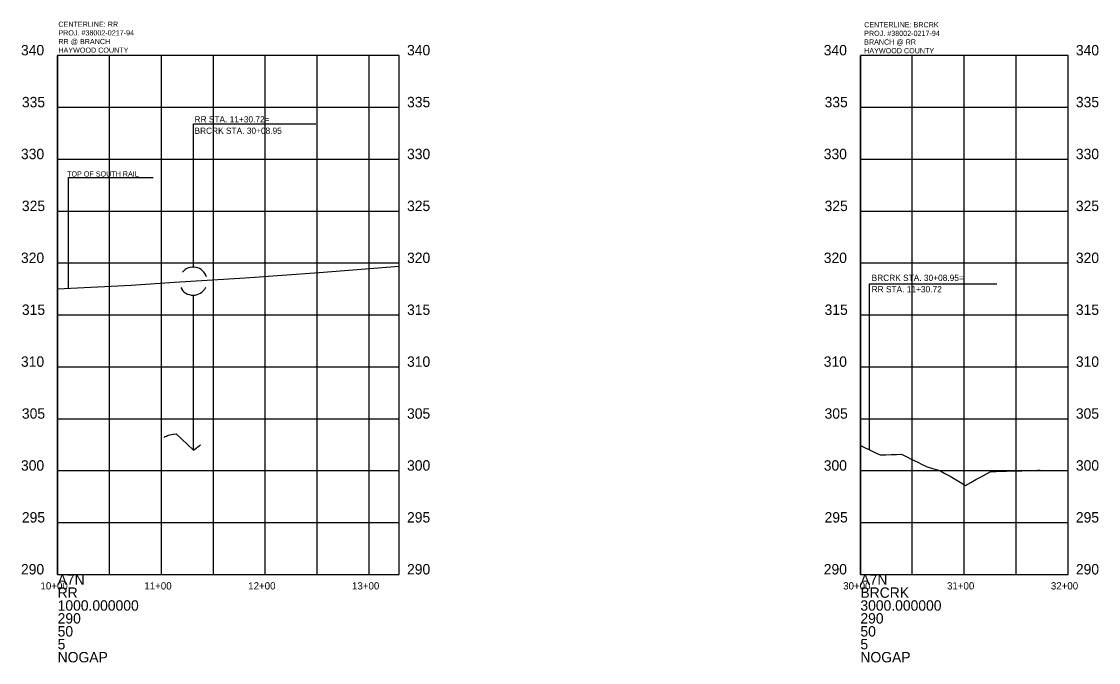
# Model space of a CAD drawing. Extents: x -200 to 952328, y -218 to 426868.
# Drawn here: x 949299 to 950336, y 425994 to 426611 of the extents above; entities that cross this region are included whole.
import ezdxf

# ---------------------------------------------------------------- set-up
doc = ezdxf.new("R2010")
doc.units = 0
for name, color, linetype in [('DESIGN - SHEET - Corner Text', 7, 'Continuous'), ('DESIGN - SHEET - Light Grid', 7, 'Continuous'), ('SURVEY - PROFILE - Drainage - Bridge Hydraulic Data with Text', 7, 'Continuous'), ('SURVEY - PROFILE - Existing Roads with Text', 7, 'Continuous'), ('SURVEY - PROFILE - Project Information and Notes', 7, 'Continuous')]:
    doc.layers.add(name, color=color, linetype=linetype)

msp = doc.modelspace()

# ---------------------------------------------------------------- linework, layer by layer
at = {"layer": 'DESIGN - SHEET - Light Grid'}
for p, q in [((949662.7, 426578.8), (949333.7, 426578.8)), ((949333.7, 426578.8), (949333.7, 426078.8)), ((949333.7, 426078.8), (949333.7, 426578.8)), ((949383.7, 426078.8), (949383.7, 426578.8)), ((949433.7, 426078.8), (949433.7, 426578.8)), ((949483.7, 426078.8), (949483.7, 426578.8)), ((949533.7, 426078.8), (949533.7, 426578.8)), ((949583.7, 426078.8), (949583.7, 426578.8)), ((949633.7, 426078.8), (949633.7, 426578.8)), ((949662.7, 426078.8), (949662.7, 426578.8)), ((950306.8, 426578.8), (950106.8, 426578.8)), ((950106.8, 426578.8), (950106.8, 426078.8)), ((950106.8, 426078.8), (950106.8, 426578.8)), ((950156.8, 426078.8), (950156.8, 426578.8)), ((950206.8, 426078.8), (950206.8, 426578.8)), ((950256.8, 426078.8), (950256.8, 426578.8)), ((950306.8, 426078.8), (950306.8, 426578.8)), ((949333.7, 426528.8), (949662.7, 426528.8)), ((950106.8, 426528.8), (950306.8, 426528.8)), ((949333.7, 426478.8), (949662.7, 426478.8)), ((950106.8, 426478.8), (950306.8, 426478.8)), ((949333.7, 426428.8), (949662.7, 426428.8)), ((950106.8, 426428.8), (950306.8, 426428.8)), ((949333.7, 426378.8), (949662.7, 426378.8)), ((950106.8, 426378.8), (950306.8, 426378.8)), ((949333.7, 426328.8), (949662.7, 426328.8)), ((950106.8, 426328.8), (950306.8, 426328.8)), ((949333.7, 426278.8), (949662.7, 426278.8)), ((950106.8, 426278.8), (950306.8, 426278.8)), ((949333.7, 426228.8), (949662.7, 426228.8)), ((950106.8, 426228.8), (950306.8, 426228.8)), ((949333.7, 426178.8), (949662.7, 426178.8)), ((950106.8, 426178.8), (950306.8, 426178.8)), ((949333.7, 426128.8), (949662.7, 426128.8)), ((950106.8, 426128.8), (950306.8, 426128.8)), ((949333.7, 426078.8), (949662.7, 426078.8)), ((949333.7, 426078.8), (949662.7, 426078.8)), ((949333.7, 426078.8), (949333.7, 426078.8)), ((950106.8, 426078.8), (950306.8, 426078.8)), ((950106.8, 426078.8), (950279.8, 426078.8)), ((950106.8, 426078.8), (950106.8, 426078.8))]:
    msp.add_line(p, q, dxfattribs=at)
at = {"layer": 'SURVEY - PROFILE - Drainage - Bridge Hydraulic Data with Text'}
for points in [[(949435.9, 426211.3), (949436.5, 426211.1), (949437.4, 426211.6), (949438.4, 426212.1), (949439.4, 426212.6), (949440.4, 426213.1), (949444.7, 426213.8), (949445.1, 426214), (949447.7, 426214.2), (949464.1, 426198.9), (949464.4, 426198.6), (949471.4, 426203.6)], [(950106.8, 426202.9), (950110.7, 426201.1), (950115.7, 426198.7), (950120.7, 426196.3), (950125.7, 426193.9), (950126.4, 426193.9), (950131.4, 426194), (950136.4, 426194.2), (950141.4, 426194.4), (950146.4, 426194.5), (950151.4, 426192.1), (950156.4, 426189.6), (950161.4, 426187.2), (950166.4, 426184.8), (950171.2, 426182.4), (950176.2, 426180.9), (950181.2, 426179.4), (950183.2, 426178.8), (950188.1, 426176.1), (950193.1, 426173.3), (950198, 426170.5), (950203, 426167.6), (950208.1, 426164.6), (950213.1, 426167.4), (950218.1, 426170.1), (950223.1, 426172.8), (950228.1, 426175.6), (950232.4, 426177.9), (950237.4, 426178.1), (950242.4, 426178.2), (950247.4, 426178.3), (950252.4, 426178.5), (950257.4, 426178.6), (950262.4, 426178.7), (950267.4, 426178.9), (950272.4, 426179), (950277.4, 426179.1), (950279.8, 426179.2)]]:
    msp.add_lwpolyline(points, dxfattribs=at)
at = {"layer": 'SURVEY - PROFILE - Existing Roads with Text'}
for p, q in [((949464.4, 426374.7), (949464.4, 426512.8)), ((949464.4, 426512.8), (949582.2, 426512.8)), ((950115.7, 426198.6), (950115.7, 426358.6)), ((950115.7, 426358.6), (950238.3, 426358.6)), ((949464.4, 426198.6), (949464.4, 426347.8))]:
    msp.add_line(p, q, dxfattribs=at)
for points in [[(949344, 426354.4), (949344, 426461), (949425.8, 426461)], [(949333.7, 426353.9), (949404.4, 426357.4), (949446.1, 426360.3), (949514.2, 426364.4), (949585.7, 426369.6), (949662.7, 426375.8)]]:
    msp.add_lwpolyline(points, dxfattribs=at)
for start, end in [(17.4291, 139.9014), (207.0664, 333.9679)]:
    msp.add_arc((949464.2, 426361.3), 13.5, start, end, dxfattribs=at)

# ---------------------------------------------------------------- texts
at = {"layer": 'DESIGN - SHEET - Corner Text'}
for s, height, p in [('340', 10, (949298.4, 426578.8)), ('340', 10, (949670.2, 426578.8)), ('340', 10, (950071.5, 426578.8)), ('340', 10, (950314.3, 426578.8)), ('335', 10, (949299.3, 426528.8)), ('335', 10, (949670.2, 426528.8)), ('335', 10, (950072.3, 426528.8)), ('335', 10, (950314.3, 426528.8)), ('330', 10, (949298.4, 426478.8)), ('330', 10, (949670.2, 426478.8)), ('330', 10, (950071.5, 426478.8)), ('330', 10, (950314.3, 426478.8)), ('325', 10, (949299.3, 426428.8)), ('325', 10, (949670.2, 426428.8)), ('325', 10, (950072.3, 426428.8)), ('325', 10, (950314.3, 426428.8)), ('320', 10, (949298.4, 426378.8)), ('320', 10, (949670.2, 426378.8)), ('320', 10, (950071.5, 426378.8)), ('320', 10, (950314.3, 426378.8)), ('315', 10, (949299.3, 426328.8)), ('315', 10, (949670.2, 426328.8)), ('315', 10, (950072.3, 426328.8)), ('315', 10, (950314.3, 426328.8)), ('310', 10, (949298.4, 426278.8)), ('310', 10, (949670.2, 426278.8)), ('310', 10, (950071.5, 426278.8)), ('310', 10, (950314.3, 426278.8)), ('305', 10, (949299.3, 426228.8)), ('305', 10, (949670.2, 426228.8)), ('305', 10, (950072.3, 426228.8)), ('305', 10, (950314.3, 426228.8)), ('300', 10, (949298.4, 426178.8)), ('300', 10, (949670.2, 426178.8)), ('300', 10, (950071.5, 426178.8)), ('300', 10, (950314.3, 426178.8)), ('295', 10, (949299.3, 426128.8)), ('295', 10, (949670.2, 426128.8)), ('295', 10, (950072.3, 426128.8)), ('295', 10, (950314.3, 426128.8)), ('290', 10, (949298.4, 426078.8)), ('290', 10, (949670.2, 426078.8)), ('290', 10, (950071.5, 426078.8)), ('290', 10, (950314.3, 426078.8)), ('10+00', 7, (949317.2, 426064.3)), ('11+00', 7, (949417.2, 426064.3)), ('12+00', 7, (949517.2, 426064.3)), ('13+00', 7, (949617.2, 426064.3)), ('30+00', 7, (950090.2, 426064.3)), ('31+00', 7, (950190.2, 426064.3)), ('32+00', 7, (950290.2, 426064.3))]:
    msp.add_text(s, height=height, dxfattribs=at).set_placement(p)
at = {"layer": 'DESIGN - SHEET - Light Grid'}
for s, p in [('A7N', (949333.7, 426068.8)), ('A7N', (950106.8, 426068.8)), ('RR', (949333.7, 426056.3)), ('BRCRK', (950106.8, 426056.3)), ('1000.000000', (949333.7, 426043.9)), ('3000.000000', (950106.8, 426043.9)), ('290', (949333.7, 426031.5)), ('290', (950106.8, 426031.5)), ('50', (949333.7, 426019)), ('50', (950106.8, 426019)), ('5', (949333.7, 426006.6)), ('5', (950106.8, 426006.6)), ('NOGAP', (949333.7, 425994.1)), ('NOGAP', (950106.8, 425994.1))]:
    msp.add_text(s, height=10, dxfattribs=at).set_placement(p)
at = {"layer": 'SURVEY - PROFILE - Existing Roads with Text'}
for s, height, p in [('RR STA. 11+30.72=', 6, (949465.5, 426514.2)), ('BRCRK STA. 30+08.95', 6, (949465.5, 426503.2)), ('TOP OF SOUTH RAIL', 5, (949342.8, 426462.1)), ('BRCRK STA. 30+08.95=', 6, (950117.6, 426361.5)), ('RR STA. 11+30.72', 6, (950117.6, 426350.5))]:
    msp.add_text(s, height=height, dxfattribs=at).set_placement(p)
at = {"layer": 'SURVEY - PROFILE - Project Information and Notes'}
for s, p in [('CENTERLINE: RR', (949334.4, 426606.3)), ('CENTERLINE: BRCRK', (950110.4, 426605.8)), ('PROJ. #38002-0217-94', (949334.4, 426598)), ('PROJ. #38002-0217-94', (950110.4, 426597.5)), ('RR @ BRANCH', (949334.4, 426589.6)), ('BRANCH @ RR', (950110.4, 426589.2)), ('HAYWOOD COUNTY', (949334.4, 426581.3)), ('HAYWOOD COUNTY', (950110.4, 426580.8))]:
    msp.add_text(s, height=4.998, dxfattribs=at).set_placement(p)

doc.saveas('drawing.dxf')
